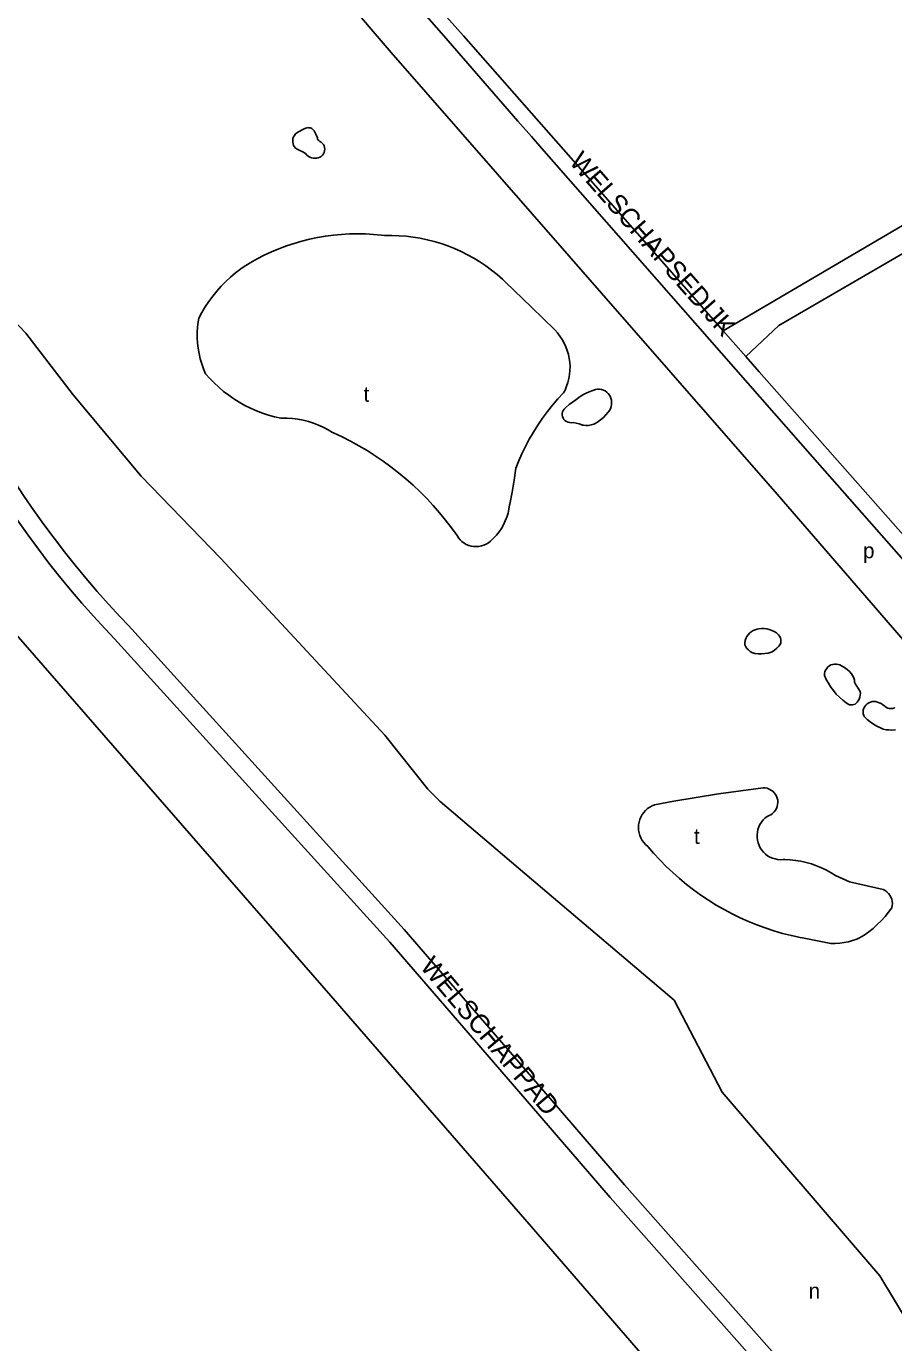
# Model space of a CAD drawing. Extents: x 156066 to 157805, y 383432 to 385631.
# Drawn here: x 156957.2 to 157183.1, y 384159.6 to 384502.5 of the extents above; entities that cross this region are included whole.
import ezdxf

# ---------------------------------------------------------------- set-up
doc = ezdxf.new("R2010")
doc.units = 0
for name, color, linetype in [('BLT_Basislijn', 7, 'Continuous'), ('BLT_Centroide', 7, 'Continuous'), ('BLT_Straatnaam', 7, 'Continuous')]:
    doc.layers.add(name, color=color, linetype=linetype)

msp = doc.modelspace()

# ---------------------------------------------------------------- linework, layer by layer
at = {"layer": 'BLT_Basislijn'}
for p, q in [((157042.7, 384526.65), (157065.9, 384500)), ((157052.19, 384495.7), (157026.05, 384526.43)), ((157066.67, 384504.99), (157071.06, 384500)), ((157065.9, 384500), (157085.24, 384477.79)), ((157071.06, 384500), (157088.75, 384479.89)), ((157269.37, 384500), (157138.64, 384423.17)), ((157088.75, 384479.89), (157138.64, 384423.17)), ((157153.14, 384424.57), (157251.62, 384481.8)), ((157085.24, 384477.79), (157088.75, 384473.76)), ((157088.75, 384473.76), (157091.45, 384470.65)), ((157091.45, 384470.65), (157161.96, 384390.33)), ((157082.01, 384435.87), (157088.75, 384429.32)), ((157088.75, 384429.32), (157094.82, 384423.41)), ((157153.14, 384424.57), (157144.54, 384416.47)), ((157138.64, 384423.17), (157144.54, 384416.47)), ((157144.54, 384416.47), (157148.04, 384412.49)), ((157148.04, 384412.49), (157225.04, 384325.21)), ((157161.96, 384390.33), (157250.85, 384289.34)), ((157174.37, 384329.25), (157173.48, 384330.65)), ((157159.32, 384265.04), (157166.74, 384263.63)), ((157036.49, 384250), (157088.75, 384189.77)), ((157088.75, 384189.77), (157156.52, 384111.66))]:
    msp.add_line(p, q, dxfattribs=at)
for points in [[(157463.86, 384023.42), (157317.96, 384189.64), (157152.75, 384380.64), (157052.19, 384495.7)], [(157030.52, 384476.11), (157029.75, 384475.86), (157029.01, 384475.54), (157028.3, 384475.14), (157028.08, 384475)], [(157032.12, 384475.35), (157031.87, 384475.64), (157031.55, 384475.86), (157031.2, 384476.02), (157030.83, 384476.1), (157030.52, 384476.11)], [(157033.01, 384473.48), (157032.64, 384474.38), (157032.19, 384475.24), (157032.12, 384475.35)], [(157028.08, 384475), (157027.68, 384474.76), (157027.33, 384474.46), (157027.04, 384474.1), (157026.81, 384473.7), (157026.66, 384473.27), (157026.59, 384472.82), (157026.59, 384472.36), (157026.67, 384471.9), (157026.83, 384471.47), (157027.07, 384471.07), (157027.32, 384470.77)], [(157033.59, 384472.59), (157033.36, 384472.74), (157033.17, 384472.95), (157033.05, 384473.21), (157033.01, 384473.48)], [(157034.35, 384472.01), (157034.04, 384472.31), (157033.69, 384472.54), (157033.59, 384472.59)], [(157034.88, 384470.15), (157034.93, 384470.54), (157034.9, 384470.95), (157034.79, 384471.33), (157034.61, 384471.69), (157034.35, 384472.01)], [(157027.32, 384470.77), (157027.93, 384470.38), (157028.59, 384470.06), (157029.05, 384469.88)], [(157029.05, 384469.88), (157029.49, 384469.65), (157029.88, 384469.35), (157030.26, 384468.94)], [(157030.26, 384468.94), (157030.63, 384468.64), (157031.04, 384468.4), (157031.49, 384468.23), (157031.97, 384468.15), (157032.45, 384468.14), (157032.84, 384468.19)], [(157032.84, 384468.19), (157033.25, 384468.26), (157033.65, 384468.41), (157034.01, 384468.63), (157034.32, 384468.92), (157034.57, 384469.25), (157034.76, 384469.63), (157034.87, 384470.04), (157034.88, 384470.15)], [(157013.69, 384439.79), (157015.47, 384440.89), (157017.3, 384441.91), (157019.17, 384442.87), (157021.07, 384443.76), (157023, 384444.57), (157024.96, 384445.3), (157026.95, 384445.97), (157028.96, 384446.55), (157030.99, 384447.06), (157033.05, 384447.49), (157035.11, 384447.84), (157037.19, 384448.11), (157039.28, 384448.31), (157041.37, 384448.42), (157043.47, 384448.46), (157045.56, 384448.41), (157047.65, 384448.28), (157049.74, 384448.08), (157050.52, 384447.98)], [(157050.52, 384447.98), (157052.38, 384448), (157054.24, 384447.94), (157056.1, 384447.8), (157057.96, 384447.58), (157059.8, 384447.28), (157061.62, 384446.9), (157063.43, 384446.44), (157065.22, 384445.91), (157066.98, 384445.3), (157068.71, 384444.61), (157070.42, 384443.85), (157072.09, 384443.02), (157073.72, 384442.12), (157075.31, 384441.15), (157076.86, 384440.11), (157078.37, 384439.01), (157079.82, 384437.84), (157081.22, 384436.61), (157082.01, 384435.87)], [(157002.12, 384426.44), (157002.93, 384427.94), (157003.8, 384429.41), (157004.75, 384430.83), (157005.76, 384432.21), (157006.83, 384433.54), (157007.97, 384434.81), (157009.16, 384436.03), (157010.41, 384437.2), (157011.71, 384438.3), (157013.07, 384439.35), (157013.69, 384439.79)], [(156949.17, 384430.83), (156957.08, 384422.59), (156969.42, 384406.53)], [(156880.07, 384429.75), (156931.65, 384370.28), (157036.49, 384250)], [(157003.9, 384412.02), (157003.36, 384413.29), (157002.89, 384414.6), (157002.5, 384415.92), (157002.19, 384417.27), (157001.95, 384418.63), (157001.79, 384420.01), (157001.72, 384421.39), (157001.72, 384422.77), (157001.8, 384424.15), (157001.97, 384425.53), (157002.12, 384426.44)], [(157094.82, 384423.41), (157095.53, 384422.63), (157096.18, 384421.8), (157096.76, 384420.92), (157097.28, 384420), (157097.72, 384419.04), (157098.09, 384418.05), (157098.39, 384417.04), (157098.61, 384416.01), (157098.74, 384414.96), (157098.8, 384413.91), (157098.78, 384412.85), (157098.68, 384411.8), (157098.5, 384410.76), (157098.24, 384409.74), (157097.91, 384408.74), (157097.5, 384407.76), (157097.13, 384407.04)], [(157023.47, 384400.45), (157021.86, 384400.81), (157020.26, 384401.25), (157018.68, 384401.77), (157017.14, 384402.36), (157015.62, 384403.03), (157014.14, 384403.76), (157012.69, 384404.57), (157011.28, 384405.45), (157009.92, 384406.4), (157008.61, 384407.41), (157007.35, 384408.48), (157006.14, 384409.61), (157004.98, 384410.8), (157003.9, 384412.02)], [(157097.13, 384407.04), (157095.67, 384405.46), (157094.26, 384403.83), (157092.91, 384402.15), (157091.63, 384400.42), (157090.41, 384398.65), (157089.26, 384396.83), (157088.75, 384395.94)], [(157100.31, 384405.21), (157101.11, 384405.84), (157101.96, 384406.4), (157102.84, 384406.9), (157103.76, 384407.32), (157104.72, 384407.67), (157105.43, 384407.88)], [(157105.43, 384407.88), (157105.95, 384407.97), (157106.47, 384407.97), (157106.99, 384407.9), (157107.49, 384407.75), (157107.96, 384407.52), (157108.39, 384407.23), (157108.77, 384406.87), (157109.09, 384406.46), (157109.26, 384406.19)], [(156969.42, 384406.53), (156987.16, 384385.32), (157007.89, 384363.92), (157050.56, 384317.86), (157061.77, 384303.77), (157064.95, 384300.59)], [(157100.31, 384405.21), (157099.42, 384404.63), (157098.57, 384403.99), (157097.77, 384403.29), (157097.24, 384402.76)], [(157109.26, 384406.19), (157109.46, 384405.66), (157109.59, 384405.11), (157109.64, 384404.55), (157109.6, 384403.99), (157109.49, 384403.43), (157109.3, 384402.9), (157109.04, 384402.4), (157108.77, 384402.01)], [(157036.99, 384396.71), (157035.8, 384397.42), (157034.56, 384398.06), (157033.29, 384398.63), (157031.99, 384399.12), (157030.66, 384399.54), (157029.31, 384399.88), (157027.95, 384400.14), (157026.57, 384400.33), (157025.18, 384400.43), (157023.79, 384400.46), (157023.47, 384400.45)], [(157097.24, 384402.76), (157097.01, 384402.43), (157096.85, 384402.05), (157096.77, 384401.65), (157096.76, 384401.25), (157096.84, 384400.85), (157096.99, 384400.47), (157097.21, 384400.13), (157097.49, 384399.83), (157097.91, 384399.56)], [(157108.77, 384402.01), (157108.16, 384401.28), (157107.49, 384400.6), (157106.77, 384399.99), (157105.99, 384399.43), (157105.18, 384398.95), (157104.99, 384398.85)], [(157069.38, 384369.83), (157067.93, 384371.86), (157066.41, 384373.85), (157064.83, 384375.78), (157063.2, 384377.66), (157061.5, 384379.49), (157059.74, 384381.26), (157057.93, 384382.98), (157056.06, 384384.63), (157054.15, 384386.23), (157052.18, 384387.76), (157050.16, 384389.23), (157048.1, 384390.64), (157045.99, 384391.98), (157043.84, 384393.25), (157041.65, 384394.45), (157039.43, 384395.58), (157037.17, 384396.63), (157036.99, 384396.71)], [(157097.91, 384399.56), (157098.3, 384399.38), (157098.73, 384399.27), (157099.16, 384399.24), (157099.6, 384399.29)], [(157099.6, 384399.29), (157100.39, 384399.17), (157101.16, 384398.96), (157101.91, 384398.68), (157102.05, 384398.62)], [(157104.99, 384398.85), (157104.32, 384398.66), (157103.64, 384398.56), (157102.96, 384398.53), (157102.27, 384398.59), (157102.05, 384398.62)], [(157088.75, 384395.94), (157088.18, 384394.97), (157087.17, 384393.07), (157086.23, 384391.13), (157085.36, 384389.16), (157084.68, 384387.45)], [(157084.68, 384387.45), (157084.23, 384384.29), (157083.71, 384381.14), (157083.11, 384378), (157083.08, 384377.84)], [(156954.24, 384383.79), (156956.7, 384380.07), (156959.22, 384376.38), (156961.81, 384372.75), (156964.46, 384369.16), (156967.18, 384365.61), (156969.95, 384362.12), (156972.8, 384358.68), (156975.7, 384355.29), (156978.66, 384351.95), (156981.68, 384348.66), (156983.83, 384346.4)], [(156950.04, 384381.08), (156952.52, 384377.32), (156955.07, 384373.6), (156957.68, 384369.92), (156960.36, 384366.29), (156963.1, 384362.71), (156965.9, 384359.18), (156968.76, 384355.7), (156971.69, 384352.27), (156974.68, 384348.9), (156977.72, 384345.57), (156980.22, 384342.93)], [(157083.08, 384377.84), (157082.91, 384376.77), (157082.67, 384375.71), (157082.34, 384374.67), (157081.95, 384373.66), (157081.47, 384372.68), (157080.93, 384371.73), (157080.32, 384370.83), (157079.65, 384369.98), (157078.91, 384369.18), (157078.1, 384368.41)], [(157078.1, 384368.41), (157077.57, 384367.99), (157076.99, 384367.64), (157076.38, 384367.36), (157075.74, 384367.15), (157075.07, 384367.02), (157074.4, 384366.97), (157073.73, 384367), (157073.06, 384367.11), (157072.41, 384367.3), (157071.79, 384367.56), (157071.21, 384367.89), (157070.67, 384368.29), (157070.17, 384368.76), (157069.74, 384369.27), (157069.38, 384369.83)], [(156983.83, 384346.4), (157055.62, 384267.29), (157088.75, 384228.89)], [(157147.55, 384345.47), (157147, 384345.32), (157146.48, 384345.1), (157146, 384344.8), (157145.56, 384344.44), (157145.18, 384344.02), (157144.86, 384343.55), (157144.61, 384343.04), (157144.43, 384342.51), (157144.33, 384341.95), (157144.31, 384341.41)], [(157153.12, 384343.99), (157152.54, 384344.49), (157151.96, 384344.86), (157151.34, 384345.17), (157150.69, 384345.41), (157150.02, 384345.56), (157149.33, 384345.64), (157148.64, 384345.64), (157147.96, 384345.56), (157147.55, 384345.47)], [(156980.22, 384342.93), (157051.87, 384263.98), (157088.75, 384221.24)], [(157144.31, 384341.41), (157144.56, 384340.91), (157144.87, 384340.46), (157145.24, 384340.05), (157145.67, 384339.7), (157146.15, 384339.41), (157146.66, 384339.2), (157146.93, 384339.12)], [(157151.4, 384339.55), (157152.05, 384340), (157152.65, 384340.5), (157153.2, 384341.07), (157153.54, 384341.49)], [(157153.54, 384341.49), (157153.67, 384341.92), (157153.71, 384342.36), (157153.68, 384342.8), (157153.57, 384343.23), (157153.38, 384343.62), (157153.12, 384343.99)], [(157146.93, 384339.12), (157147.79, 384339.04), (157148.65, 384339.03), (157149.51, 384339.1), (157150.36, 384339.26), (157151.19, 384339.49), (157151.4, 384339.55)], [(157169.5, 384335.93), (157169.08, 384336.16), (157168.63, 384336.31), (157168.16, 384336.39), (157167.68, 384336.39), (157167.2, 384336.31), (157166.75, 384336.16), (157166.33, 384335.92), (157165.95, 384335.63), (157165.63, 384335.27), (157165.37, 384334.87), (157165.18, 384334.43), (157165.07, 384333.96), (157165.04, 384333.43)], [(157172.08, 384333.85), (157171.54, 384334.45), (157170.93, 384334.99), (157170.29, 384335.47), (157169.5, 384335.93)], [(157165.04, 384333.43), (157165.52, 384332.38), (157166.08, 384331.37), (157166.7, 384330.39), (157167.39, 384329.46), (157168.14, 384328.58), (157168.96, 384327.76), (157169.82, 384326.99), (157170.74, 384326.28), (157170.89, 384326.18)], [(157172.88, 384332.16), (157172.67, 384332.78), (157172.38, 384333.37), (157172.08, 384333.85)], [(157173.48, 384330.65), (157173.23, 384330.95), (157173.04, 384331.3), (157172.92, 384331.68), (157172.88, 384332.16)], [(157173.54, 384326.43), (157173.86, 384326.83), (157174.11, 384327.28), (157174.29, 384327.76), (157174.39, 384328.26), (157174.42, 384328.77), (157174.37, 384329.25)], [(157170.89, 384326.18), (157171.2, 384325.96), (157171.55, 384325.81), (157171.92, 384325.73), (157172.3, 384325.73), (157172.68, 384325.82), (157173.03, 384325.97), (157173.33, 384326.2), (157173.54, 384326.43)], [(157175.12, 384324.25), (157175.1, 384323.81), (157175.16, 384323.38), (157175.3, 384322.96), (157175.45, 384322.66)], [(157179.34, 384326.3), (157178.9, 384326.49), (157178.43, 384326.61), (157177.96, 384326.65), (157177.48, 384326.61), (157177.01, 384326.49), (157176.57, 384326.3), (157176.17, 384326.03), (157175.82, 384325.7), (157175.53, 384325.32), (157175.31, 384324.9), (157175.16, 384324.44), (157175.12, 384324.25)], [(157179.34, 384326.3), (157179.82, 384326.09), (157180.27, 384325.81), (157180.67, 384325.47), (157180.82, 384325.32)], [(157180.82, 384325.32), (157181.17, 384325.07), (157181.56, 384324.89), (157181.98, 384324.79), (157182.41, 384324.77), (157182.84, 384324.82), (157183.25, 384324.96), (157183.42, 384325.04)], [(157175.45, 384322.66), (157176.19, 384321.95), (157176.98, 384321.3), (157177.81, 384320.72), (157178.69, 384320.2), (157179.61, 384319.75), (157180.37, 384319.45)], [(157180.37, 384319.45), (157181.16, 384319.29), (157181.74, 384319.22)], [(157181.74, 384319.22), (157182.62, 384319.19), (157183.55, 384319.25)], [(157149.1, 384304.14), (157143.27, 384303.39), (157137.46, 384302.56), (157131.65, 384301.65), (157125.86, 384300.66), (157120.84, 384299.73)], [(157150.1, 384296.72), (157150.62, 384296.9), (157151.11, 384297.15), (157151.56, 384297.47), (157151.95, 384297.86), (157152.29, 384298.29), (157152.56, 384298.77), (157152.75, 384299.28), (157152.87, 384299.82), (157152.91, 384300.36), (157152.88, 384300.91), (157152.76, 384301.45), (157152.56, 384301.96), (157152.3, 384302.44), (157151.96, 384302.88), (157151.57, 384303.26), (157151.12, 384303.58), (157150.64, 384303.84), (157150.12, 384304.02), (157149.58, 384304.12), (157149.1, 384304.14)], [(157064.95, 384300.59), (157088.75, 384280.38)], [(157120.84, 384299.73), (157120.18, 384299.47), (157119.56, 384299.13), (157118.99, 384298.73), (157118.46, 384298.26), (157117.99, 384297.74), (157117.58, 384297.16), (157117.23, 384296.55), (157116.96, 384295.89), (157116.77, 384295.22), (157116.65, 384294.52), (157116.61, 384293.82), (157116.65, 384293.11), (157116.77, 384292.42), (157116.97, 384291.74), (157117.25, 384291.09), (157117.6, 384290.47), (157118.01, 384289.9), (157118.48, 384289.38), (157119.04, 384288.9)], [(157150.1, 384296.72), (157149.55, 384296.28), (157149.06, 384295.78), (157148.62, 384295.22), (157148.25, 384294.62), (157147.95, 384293.98), (157147.73, 384293.31), (157147.58, 384292.62), (157147.51, 384291.92), (157147.52, 384291.21), (157147.61, 384290.51), (157147.78, 384289.83), (157148.02, 384289.16), (157148.34, 384288.53), (157148.73, 384287.94), (157149.18, 384287.4), (157149.69, 384286.91), (157150.25, 384286.48), (157150.86, 384286.12), (157151.5, 384285.83), (157152.18, 384285.62), (157152.87, 384285.48), (157153.57, 384285.42), (157154.28, 384285.44), (157154.71, 384285.49)], [(157119.04, 384288.9), (157120.57, 384287.11), (157122.17, 384285.38), (157123.82, 384283.7), (157125.53, 384282.07), (157127.3, 384280.51), (157129.11, 384279), (157130.98, 384277.56), (157132.89, 384276.18), (157134.85, 384274.87), (157136.85, 384273.63), (157138.9, 384272.45), (157140.98, 384271.35), (157143.1, 384270.31), (157145.25, 384269.35), (157147.44, 384268.46), (157149.65, 384267.65), (157151.89, 384266.91), (157154.15, 384266.25), (157156.44, 384265.66), (157158.74, 384265.15), (157159.32, 384265.04)], [(157154.71, 384285.49), (157156.13, 384285.42), (157157.53, 384285.26), (157158.93, 384285.02), (157160.3, 384284.7), (157161.66, 384284.31), (157163, 384283.84), (157164.3, 384283.3), (157165.58, 384282.68), (157166.81, 384281.99), (157167.94, 384281.28)], [(157088.75, 384280.38), (157125.95, 384248.8), (157138.38, 384224.9), (157179.5, 384177.08), (157199.58, 384143.61), (157248.35, 384085.28), (157269.97, 384055.34), (157304.71, 384024.5), (157340.39, 383985.23), (157391.35, 383930.37), (157420.88, 383940.11), (157470.65, 383958.4), (157478.75, 383966.19), (157481.29, 383979.08), (157476.65, 383991.08), (157465.85, 384006.22), (157459.4, 384019.12), (157463.86, 384023.42)], [(157167.94, 384281.28), (157171.55, 384279.68), (157180.37, 384277.67)], [(157180.37, 384277.67), (157180.87, 384277.4), (157181.33, 384277.06), (157181.73, 384276.66), (157182.08, 384276.21), (157182.35, 384275.71), (157182.56, 384275.18), (157182.69, 384274.63), (157182.74, 384274.06), (157182.71, 384273.5), (157182.58, 384272.86)], [(157174.16, 384265.04), (157175.39, 384265.81), (157176.58, 384266.64), (157177.73, 384267.54), (157178.82, 384268.51), (157179.85, 384269.53), (157180.83, 384270.6), (157181.75, 384271.73), (157182.58, 384272.86)], [(157166.74, 384263.63), (157167.88, 384263.62), (157169.02, 384263.69), (157170.16, 384263.84), (157171.28, 384264.06), (157172.38, 384264.36), (157173.46, 384264.74), (157174.16, 384265.04)], [(157088.75, 384228.89), (157113.01, 384200.77), (157176.31, 384129.21)], [(157088.75, 384221.24), (157109.24, 384197.48), (157172.52, 384125.95)]]:
    msp.add_lwpolyline(points, dxfattribs=at)

# ---------------------------------------------------------------- texts
at = {"layer": 'BLT_Centroide'}
for s, p in [('t', (157045.04, 384404.71)), ('p', (157175.11, 384363.95)), ('t', (157131.07, 384289.54)), ('n', (157160.93, 384171.13))]:
    msp.add_text(s, height=4, dxfattribs=at).set_placement(p)
at = {"layer": 'BLT_Straatnaam'}
for s, height, rotation, p in [('WELSCHAPSEDIJK', 4.9999, 311.3225, (157098.36, 384467.07)), ('WELSCHAPPAD', 5, 310.1929, (157059.54, 384257.49))]:
    msp.add_text(s, height=height, rotation=rotation, dxfattribs=at).set_placement(p)

doc.saveas('drawing.dxf')
